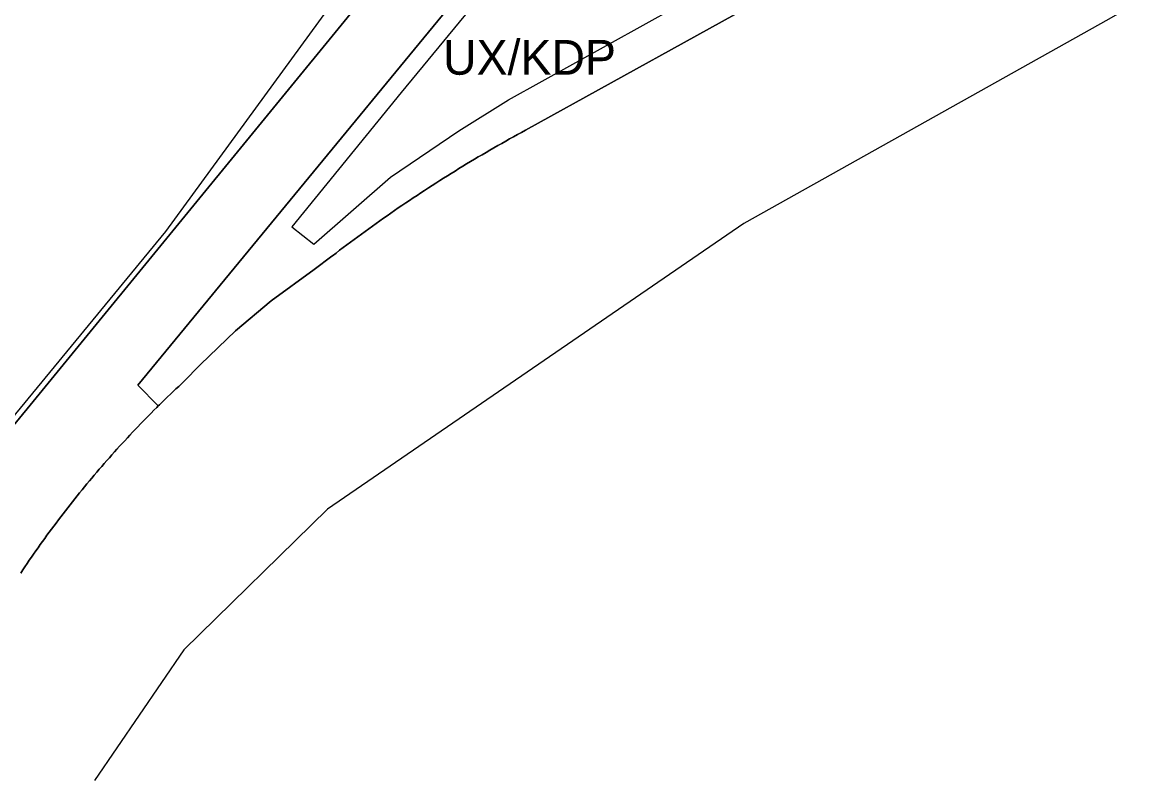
# Model space of a CAD drawing. Extents: x -297746 to -295403, y 27112 to 28877.
# Drawn here: x -296302 to -295980.2, y 27909.6 to 28126 of the extents above; entities that cross this region are included whole.
import ezdxf

# ---------------------------------------------------------------- set-up
doc = ezdxf.new("R2010")
doc.units = 0
for name, color, linetype in [('linie_rozgraniczajace', 7, 'Continuous'), ('linie_zabudowy_nieprzekraczalne', 7, 'Continuous'), ('linie_zabudowy_obowiazujace', 7, 'Continuous'), ('oznaczenia_przeznaczen', 7, 'Continuous')]:
    doc.layers.add(name, color=color, linetype=linetype)

msp = doc.modelspace()

# ---------------------------------------------------------------- linework, layer by layer
at = {"layer": 'linie_rozgraniczajace'}
for points in [[(-295857.552, 28202.628), (-295989.362, 28126.879), (-296094.47, 28068.102), (-296214.214, 27985.807), (-296255.594, 27945.248), (-296281.298, 27907.627)], [(-296369.501, 27930.579), (-296150.685, 28198.209)], [(-296150.685, 28198.209), (-296369.501, 27930.579)], [(-296135.95, 28183.091), (-296268.845, 28021.49), (-296262.925, 28015.496), (-296263.393, 28015.033), (-296264.175, 28014.254), (-296264.953, 28013.473), (-296265.729, 28012.689), (-296266.502, 28011.902), (-296267.272, 28011.113), (-296268.039, 28010.32), (-296268.803, 28009.525), (-296269.565, 28008.727), (-296270.323, 28007.927), (-296271.079, 28007.123), (-296271.832, 28006.317), (-296272.581, 28005.508), (-296273.328, 28004.696), (-296274.072, 28003.882), (-296274.813, 28003.065), (-296275.551, 28002.246), (-296276.286, 28001.423), (-296277.018, 28000.598), (-296277.747, 27999.771), (-296278.473, 27998.94), (-296279.196, 27998.107), (-296279.915, 27997.272), (-296280.632, 27996.434), (-296281.346, 27995.593), (-296282.057, 27994.75), (-296282.765, 27993.904), (-296283.469, 27993.055), (-296284.171, 27992.204), (-296284.869, 27991.351), (-296285.565, 27990.495), (-296286.257, 27989.636), (-296286.946, 27988.775), (-296287.632, 27987.911), (-296288.315, 27987.045), (-296288.995, 27986.177), (-296289.671, 27985.306), (-296290.345, 27984.432), (-296291.015, 27983.556), (-296291.682, 27982.678), (-296292.346, 27981.797), (-296293.007, 27980.914), (-296293.664, 27980.029), (-296294.318, 27979.141), (-296294.969, 27978.251), (-296295.617, 27977.358), (-296296.262, 27976.463), (-296296.903, 27975.566), (-296297.541, 27974.666), (-296298.176, 27973.764), (-296298.807, 27972.86), (-296299.436, 27971.953), (-296300.06, 27971.045), (-296300.682, 27970.134), (-296301.3, 27969.22), (-296301.915, 27968.305), (-296302.527, 27967.387)], [(-296262.925, 28015.496), (-296268.845, 28021.49), (-296135.95, 28183.091)], [(-296083.268, 28135.975), (-296157.274, 28094.933), (-296158.416, 28094.309), (-296159.556, 28093.682), (-296160.693, 28093.051), (-296161.829, 28092.416), (-296162.963, 28091.778), (-296164.095, 28091.137), (-296165.225, 28090.492), (-296166.353, 28089.843), (-296167.479, 28089.191), (-296168.602, 28088.536), (-296169.724, 28087.877), (-296170.844, 28087.215), (-296171.962, 28086.549), (-296173.078, 28085.88), (-296174.191, 28085.207), (-296175.303, 28084.531), (-296176.413, 28083.852), (-296177.52, 28083.169), (-296178.625, 28082.483), (-296179.728, 28081.793), (-296180.83, 28081.1), (-296181.929, 28080.404), (-296183.025, 28079.704), (-296184.12, 28079.001), (-296185.212, 28078.294), (-296186.303, 28077.584), (-296187.391, 28076.871), (-296188.477, 28076.155), (-296189.561, 28075.435), (-296190.642, 28074.712), (-296191.721, 28073.985), (-296192.798, 28073.255), (-296193.873, 28072.522), (-296194.946, 28071.786), (-296196.016, 28071.046), (-296197.084, 28070.303), (-296198.15, 28069.557), (-296199.213, 28068.807), (-296200.274, 28068.054), (-296201.333, 28067.298), (-296202.389, 28066.539), (-296203.443, 28065.776), (-296204.495, 28065.01), (-296205.544, 28064.241), (-296206.591, 28063.469), (-296207.636, 28062.693), (-296208.678, 28061.915), (-296209.718, 28061.133), (-296210.755, 28060.347), (-296211.79, 28059.559), (-296212.823, 28058.768), (-296212.949, 28058.671), (-296218.058, 28054.809), (-296230.46, 28045.791), (-296240.737, 28037.149), (-296250.827, 28027.437), (-296255.791, 28022.321), (-296256.235, 28021.909), (-296257.042, 28021.156)], [(-296179.728, 28081.793), (-296178.625, 28082.483), (-296177.52, 28083.169), (-296176.413, 28083.852), (-296175.303, 28084.531), (-296174.191, 28085.207), (-296173.078, 28085.88), (-296171.962, 28086.549), (-296170.844, 28087.215), (-296169.724, 28087.877), (-296168.602, 28088.536), (-296167.479, 28089.191), (-296166.353, 28089.843), (-296165.225, 28090.492), (-296164.095, 28091.137), (-296162.963, 28091.778), (-296161.829, 28092.416), (-296160.693, 28093.051), (-296159.556, 28093.682), (-296158.416, 28094.309), (-296157.274, 28094.933), (-296083.268, 28135.975)], [(-296299.436, 27971.953), (-296298.807, 27972.86), (-296298.176, 27973.764), (-296297.541, 27974.666), (-296296.903, 27975.566), (-296296.262, 27976.463), (-296295.617, 27977.358), (-296294.969, 27978.251), (-296294.318, 27979.141), (-296293.664, 27980.029), (-296293.007, 27980.914), (-296292.346, 27981.797), (-296291.682, 27982.678), (-296291.015, 27983.556), (-296290.345, 27984.432), (-296289.671, 27985.306), (-296288.995, 27986.177), (-296288.315, 27987.045), (-296287.632, 27987.911), (-296286.946, 27988.775), (-296286.257, 27989.636), (-296285.565, 27990.495), (-296284.869, 27991.351), (-296284.171, 27992.204), (-296283.469, 27993.055), (-296282.765, 27993.904), (-296282.057, 27994.75), (-296281.346, 27995.593), (-296280.632, 27996.434), (-296279.915, 27997.272), (-296279.196, 27998.107), (-296278.473, 27998.94), (-296277.747, 27999.771), (-296277.018, 28000.598), (-296276.286, 28001.423), (-296275.551, 28002.246), (-296274.813, 28003.065), (-296274.072, 28003.882), (-296273.328, 28004.696), (-296272.581, 28005.508), (-296271.832, 28006.317), (-296271.079, 28007.123), (-296270.323, 28007.927), (-296269.565, 28008.727), (-296268.803, 28009.525), (-296268.039, 28010.32), (-296267.272, 28011.113), (-296266.502, 28011.902), (-296265.729, 28012.689), (-296264.953, 28013.473), (-296264.175, 28014.254), (-296263.393, 28015.033), (-296262.925, 28015.496), (-296262.609, 28015.808), (-296261.822, 28016.581), (-296261.032, 28017.351), (-296260.24, 28018.117), (-296259.444, 28018.881), (-296258.646, 28019.643), (-296257.845, 28020.401), (-296257.042, 28021.156), (-296256.235, 28021.909), (-296255.791, 28022.321), (-296250.827, 28027.437), (-296240.737, 28037.149), (-296230.46, 28045.791), (-296218.058, 28054.809), (-296212.949, 28058.671), (-296212.823, 28058.768), (-296211.79, 28059.559), (-296210.755, 28060.347), (-296209.718, 28061.133), (-296208.678, 28061.915), (-296207.636, 28062.693), (-296206.591, 28063.469), (-296205.544, 28064.241), (-296204.495, 28065.01), (-296203.443, 28065.776), (-296202.389, 28066.539), (-296201.333, 28067.298), (-296200.274, 28068.054), (-296199.213, 28068.807), (-296198.15, 28069.557), (-296197.084, 28070.303), (-296196.016, 28071.046), (-296194.946, 28071.786), (-296193.873, 28072.522), (-296192.798, 28073.255), (-296191.721, 28073.985), (-296190.642, 28074.712), (-296189.561, 28075.435), (-296188.477, 28076.155), (-296187.391, 28076.871), (-296186.303, 28077.584), (-296185.212, 28078.294), (-296184.12, 28079.001), (-296183.025, 28079.704), (-296181.929, 28080.404), (-296180.83, 28081.1), (-296179.728, 28081.793)], [(-296257.042, 28021.156), (-296257.845, 28020.401), (-296258.646, 28019.643), (-296259.444, 28018.881), (-296260.24, 28018.117), (-296261.032, 28017.351), (-296261.822, 28016.581), (-296262.609, 28015.808), (-296262.925, 28015.496)], [(-296302.527, 27967.387), (-296301.915, 27968.305), (-296301.3, 27969.22), (-296300.682, 27970.134), (-296300.06, 27971.045), (-296299.436, 27971.953)]]:
    msp.add_lwpolyline(points, dxfattribs=at)
at = {"layer": 'linie_zabudowy_nieprzekraczalne'}
msp.add_lwpolyline([(-296260.782, 28065.779), (-296180.491, 28175.971), (-296158.146, 28203.301), (-296165.678, 28208.227), (-296172.301, 28211.709), (-296183.46, 28216.036), (-296190.019, 28217.942), (-296228.116, 28223.114), (-296236.121, 28224.076), (-296242.75, 28224.77), (-296248.13, 28225.264), (-296253.508, 28225.698), (-296257.663, 28225.991), (-296259.763, 28226.126), (-296402.37, 28234.945), (-296407.477, 28235.034), (-296413.394, 28235.209), (-296419.612, 28235.364), (-296427.828, 28235.627)], dxfattribs=at)
at = {"layer": 'linie_zabudowy_obowiazujace'}
for points in [[(-296109.612, 28151.54), (-296110.231, 28152.424), (-296113.008, 28156.263), (-296116.906, 28161.401), (-296120.926, 28166.422), (-296124.564, 28170.743), (-296127.933, 28174.571), (-296131.421, 28178.372), (-296133.509, 28178.187), (-296193.023, 28105.816), (-296224.507, 28067.105), (-296218.177, 28062.122), (-296196.091, 28081.381), (-296176.428, 28094.713), (-296162.121, 28103.681), (-296113.694, 28130.536)], [(-296358.283, 27947.17), (-296260.782, 28065.779)]]:
    msp.add_lwpolyline(points, dxfattribs=at)

# ---------------------------------------------------------------- texts
at = {"layer": 'oznaczenia_przeznaczen'}
msp.add_text('UX/KDP', height=10, dxfattribs=at).set_placement((-296181.002, 28110.91))

doc.saveas('drawing.dxf')
